// Mitsubishi GX Works2 project: 实例练习(多点记录+位移)   PLC: FX3U/FX3UC

PROGRAM MAIN
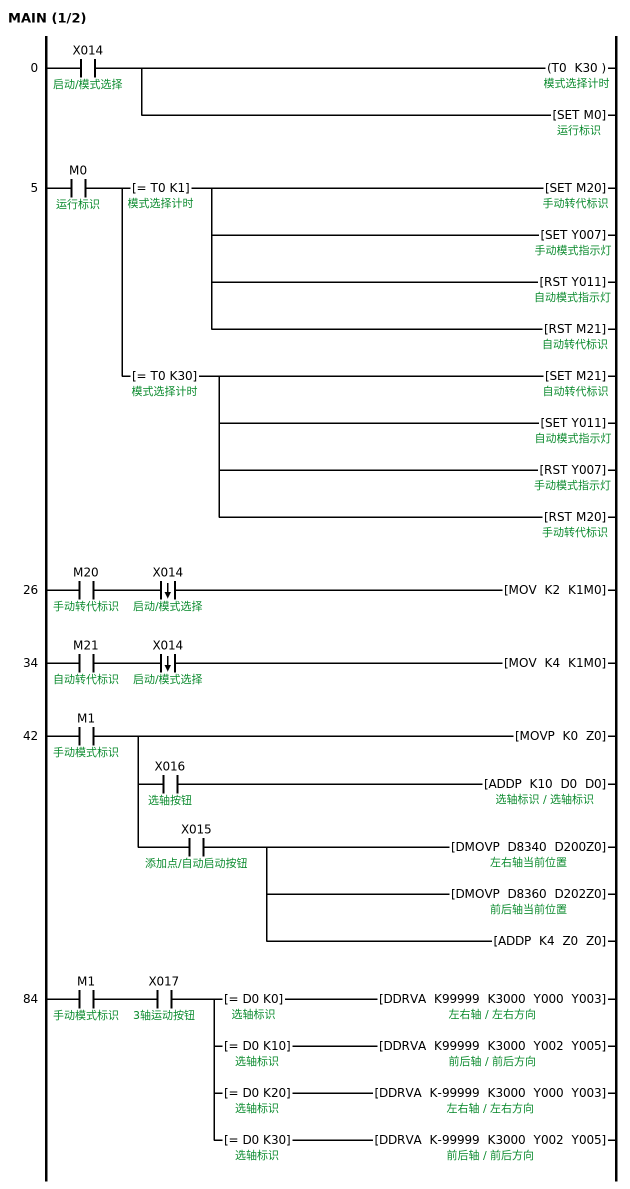
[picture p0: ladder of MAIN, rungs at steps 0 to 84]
0     LD      X014  ; 启动/模式选择
      OUT     T0 K30  ; 模式选择计时
      SET     M0  ; 运行标识
5     LD      M0  ; 运行标识
      MPS
      AND=    T0 K1  ; 模式选择计时
      SET     M20  ; 手动转代标识
      SET     Y007  ; 手动模式指示灯
      RST     Y011  ; 自动模式指示灯
      RST     M21  ; 自动转代标识
      MPP
      AND=    T0 K30  ; 模式选择计时
      SET     M21  ; 自动转代标识
      SET     Y011  ; 自动模式指示灯
      RST     Y007  ; 手动模式指示灯
      RST     M20  ; 手动转代标识
26    LD      M20  ; 手动转代标识
      ANDF    X014  ; 启动/模式选择
      MOV     K2 K1M0
34    LD      M21  ; 自动转代标识
      ANDF    X014  ; 启动/模式选择
      MOV     K4 K1M0
42    LD      M1  ; 手动模式标识
      MOVP    K0 Z0
      MPS
      AND     X016  ; 选轴按钮
      ADDP    K10 D0 D0  ; 选轴标识
      MPP
      AND     X015  ; 添加点/自动启动按钮
      DMOVP   D8340 D200Z0  ; 左右轴当前位置
      DMOVP   D8360 D202Z0  ; 前后轴当前位置
      ADDP    K4 Z0 Z0
84    LD      M1  ; 手动模式标识
      AND     X017  ; 3轴运动按钮
      MPS
      AND=    D0 K0  ; 选轴标识
      DDRVA   K99999 K3000 Y000 Y003  ; 左右轴 / 左右方向
        [note] Y0为+右行
      MRD
      AND=    D0 K10  ; 选轴标识
      DDRVA   K99999 K3000 Y002 Y005  ; 前后轴 / 前后方向
        [note] Y2为+前行
      MRD
      AND=    D0 K20  ; 选轴标识
      DDRVA   K-99999 K3000 Y000 Y003
        [note] Y0为-左行
      MPP
      AND=    D0 K30  ; 选轴标识
      DDRVA   K-99999 K3000 Y002 Y005
        [note] Y0为-后行
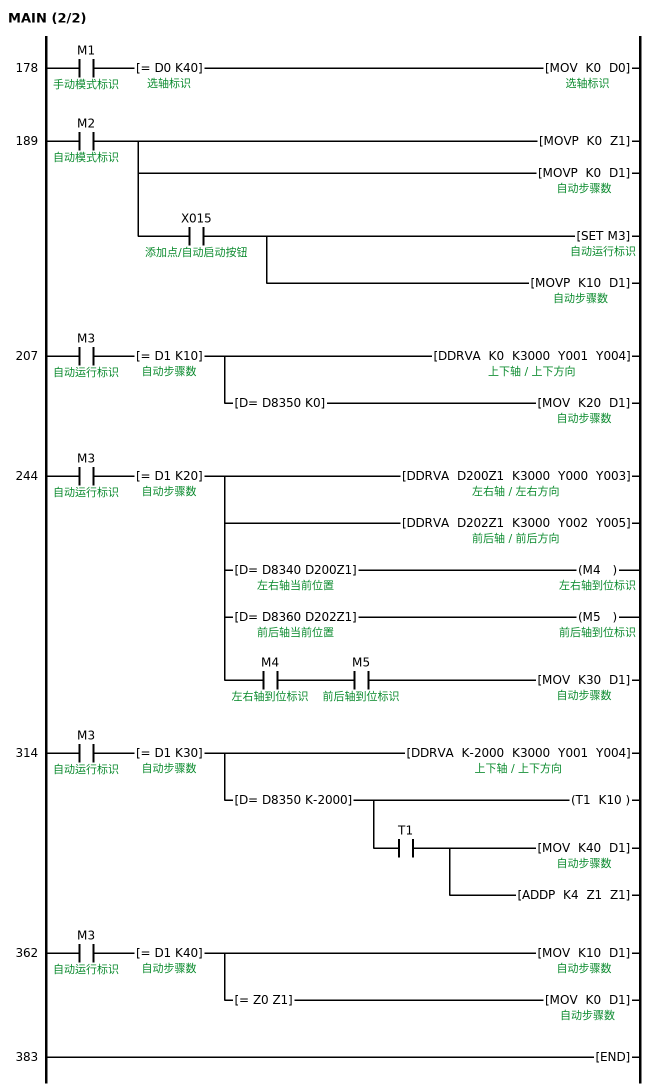
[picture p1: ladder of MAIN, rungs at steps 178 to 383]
178   LD      M1  ; 手动模式标识
      AND=    D0 K40  ; 选轴标识
      MOV     K0 D0
189   LD      M2  ; 自动模式标识
      MOVP    K0 Z1
      MOVP    K0 D1  ; 自动步骤数
      AND     X015  ; 添加点/自动启动按钮
      SET     M3  ; 自动运行标识
      MOVP    K10 D1
207   LD      M3  ; 自动运行标识
      AND=    D1 K10  ; 自动步骤数
      DDRVA   K0 K3000 Y001 Y004  ; 上下轴 / 上下方向
      ANDD=   D8350 K0
      MOV     K20 D1
244   LD      M3  ; 自动运行标识
      AND=    D1 K20  ; 自动步骤数
      DDRVA   D200Z1 K3000 Y000 Y003
      DDRVA   D202Z1 K3000 Y002 Y005
      MPS
      ANDD=   D8340 D200Z1  ; 左右轴当前位置
      OUT     M4  ; 左右轴到位标识
      MRD
      ANDD=   D8360 D202Z1  ; 前后轴当前位置
      OUT     M5  ; 前后轴到位标识
      MPP
      AND     M4  ; 左右轴到位标识
      AND     M5  ; 前后轴到位标识
      MOV     K30 D1
314   LD      M3  ; 自动运行标识
      AND=    D1 K30  ; 自动步骤数
      DDRVA   K-2000 K3000 Y001 Y004
      ANDD=   D8350 K-2000
      OUT     T1 K10
      AND     T1
      MOV     K40 D1
      ADDP    K4 Z1 Z1
362   LD      M3  ; 自动运行标识
      AND=    D1 K40  ; 自动步骤数
      MOV     K10 D1
      AND=    Z0 Z1
      MOV     K0 D1
383   END
END_PROGRAM

// device comments not shown above
D200  ; 左右轴预存位置
D202  ; 前后轴预存位置
